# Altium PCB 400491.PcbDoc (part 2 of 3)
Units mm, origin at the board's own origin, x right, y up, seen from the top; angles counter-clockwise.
Board outline 85.6 x 53.98 mm, 4 copper layers (Top Layer, Mid-Layer 1, Mid-Layer 2, Bottom Layer), stack 1.528 mm thick; 280 components, 167 nets, 927 pads, 859 vias.
Unrouted connection lines stored in the file: 24.
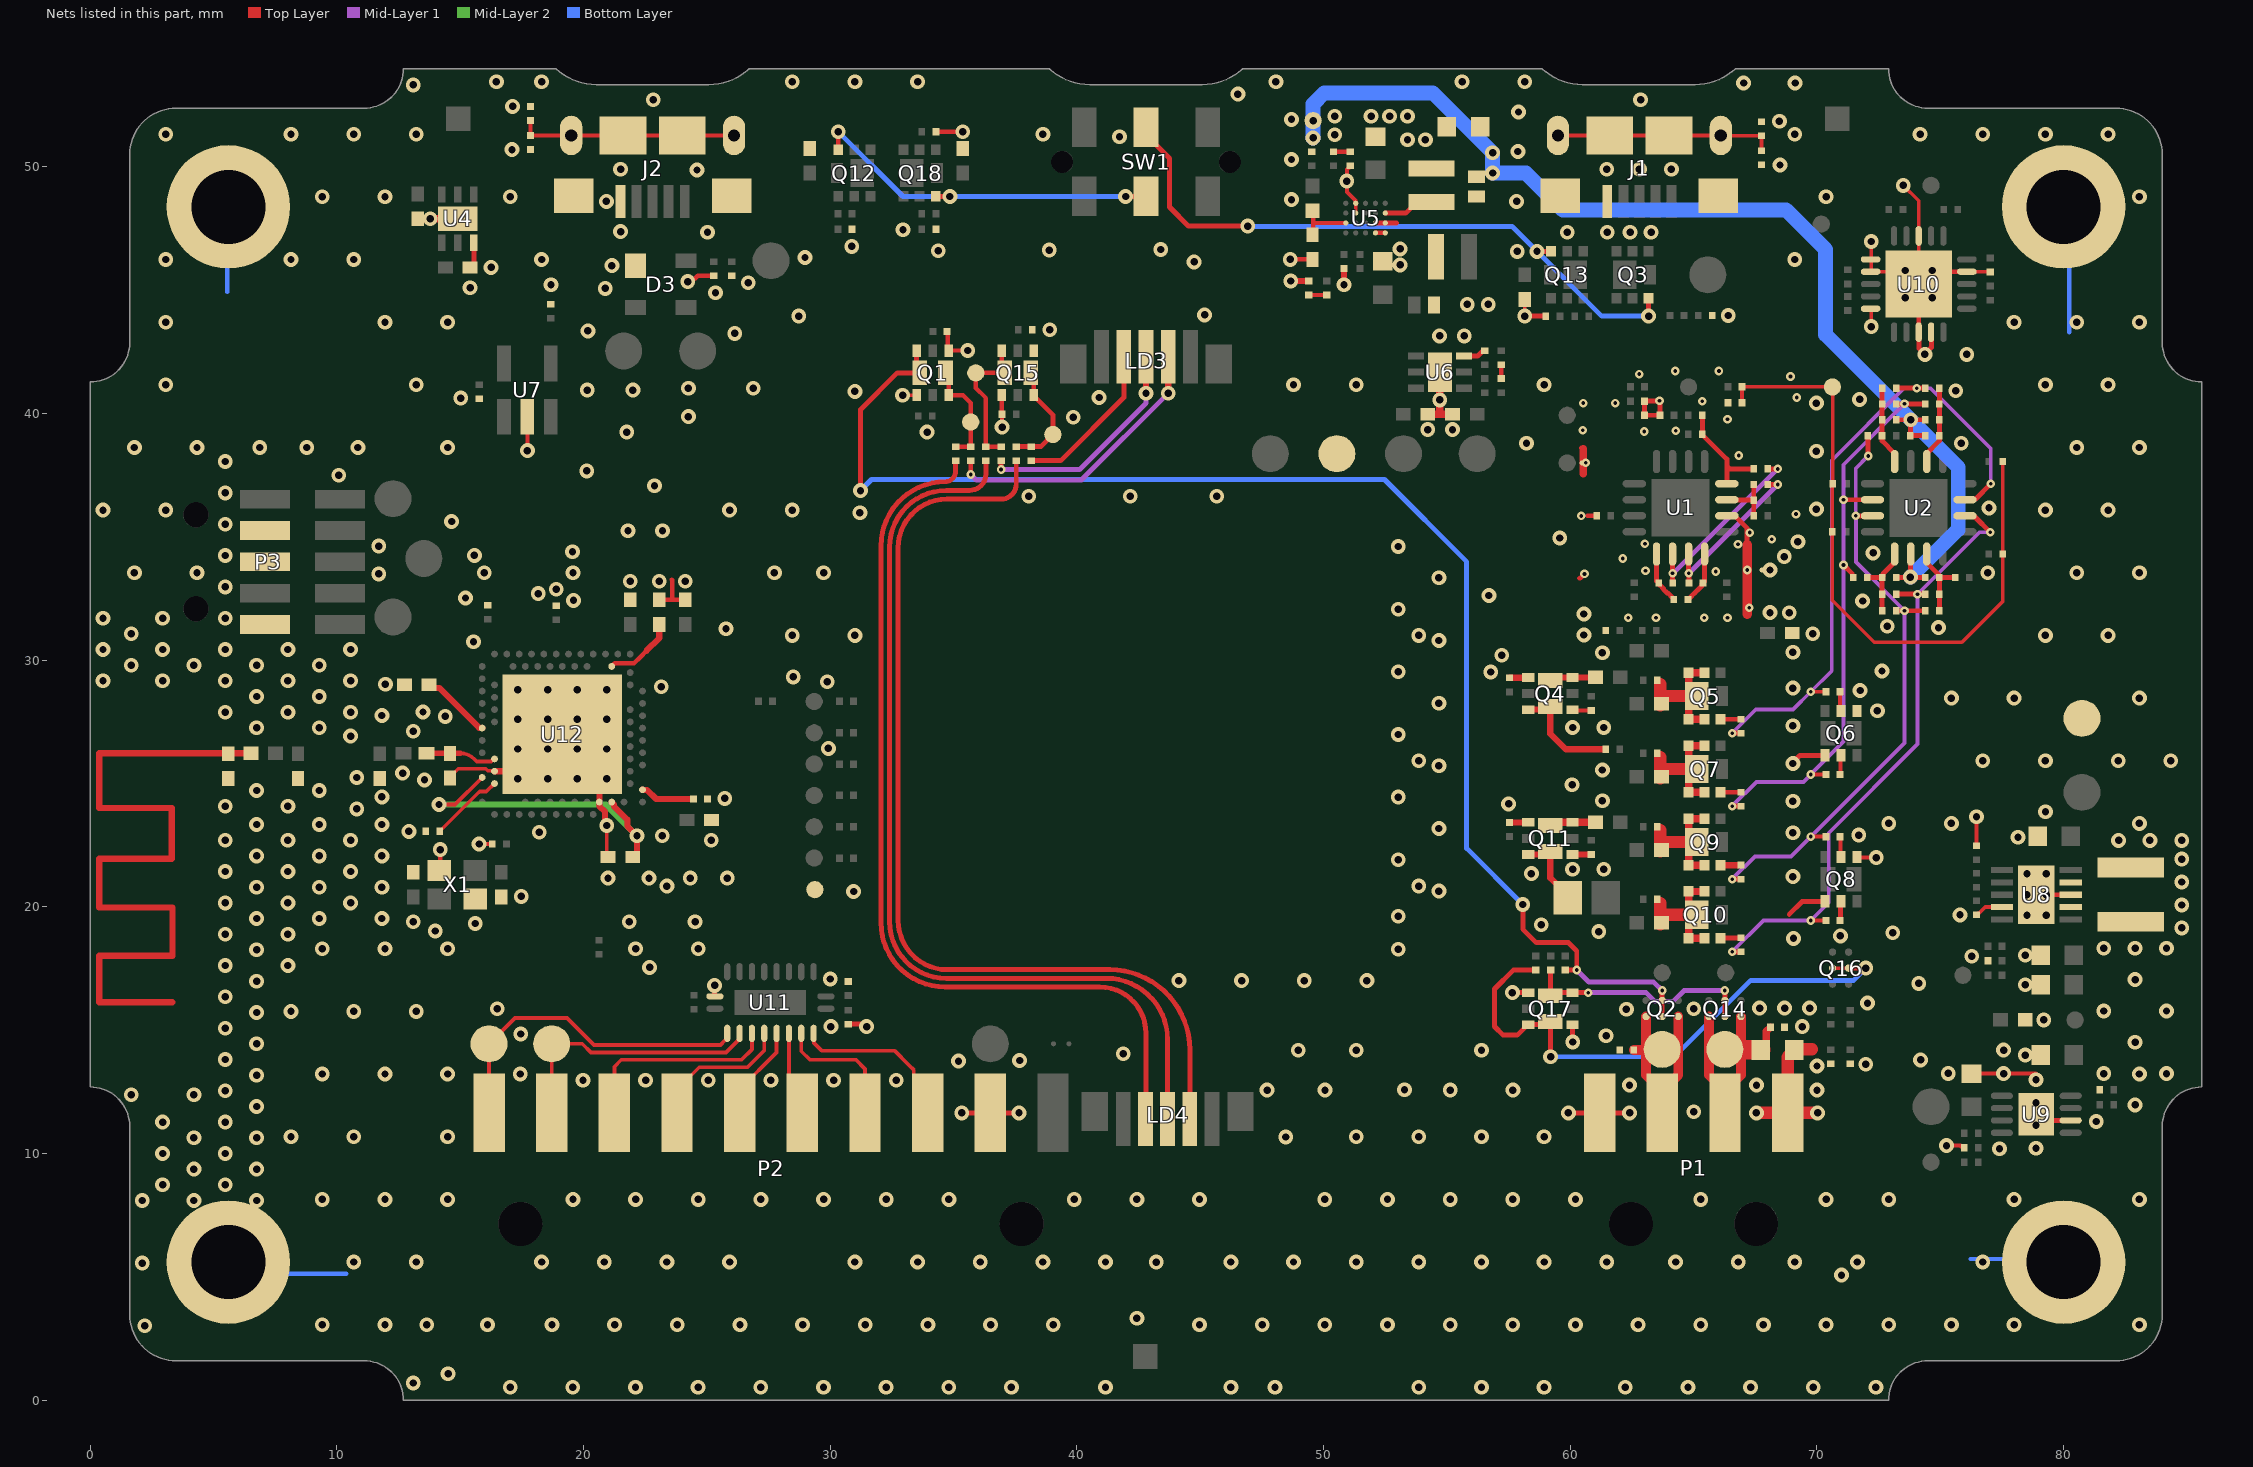
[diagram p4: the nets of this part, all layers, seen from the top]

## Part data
C1 C6: library part C0201-2.2p, "Chip Cap 0201", Part number IPS=N.A.
C2 C3 C9 C21 C22 C23 C24 C27 C46 C53 C54 C55 C60 C62 C67 C73 C75: library part C0201-100n, "Capacitor, X5R, ±10%", Part number IPS="00000001248, 00000002505"
C4 C8: library part C0201-1n0, "Capacitor, X7R, ±10%", Part number IPS=00000003206
C5 C38 C39 C44 C47 C48 C49 C50 C52: library part 0603-10u-10V-X7T-GRM188, "CAP CER 10UF 10V X7T 0603", Manufacturer=Murata, Manufacturer Part Number=GRM188D71A106MA73, Part number IPS=00000004696, Supplier Part Number 1=490-7200-1-ND
C7 C37 C42: library part C0201-2n2, "Capacitor, X7R, ±10%, 10V", Part number IPS=00000001778
C11 C14 C15 C16: library part C0201-470p, "Chip Cap 0201", Part number IPS=00000005775
C17 C19 C20 C30: library part C0201-10n, "Capacitor, X7R, ±10%", Part number IPS=00000003480
C18 C25 C26 C28 C34 C35 C41 C43 C71 C72 C74: library part C0402-4µ7, "Capacitor, X5R, ±20%", Part number IPS="00000001251, 00000007165", Supplier Part Number 1=490-13252-1-ND
C29 C33: library part C0201-4n7, "Chip Cap 0201", Part number IPS=00000001243
C40 C56 C61: library part C0402-1µ0, "Capacitor, X5R, ±5%, 6.3V", Part number IPS="00000007786, 00000003457", Supplier Part Number 1=1276-1444-1-ND
C45: library part C0201-1µ0, "Capacitor, X5R, ±10%", Part number IPS=00000001723, Supplier Part Number 1=1276-6795-1-ND
C57 C59: library part C0402-12p, "Capacitor, NP0, ±2%", Part number IPS=00000002398
C63: library part C0201-100p, "Capacitor, NP0, ±2%, 25V", Manufacturer=Murata, Manufacturer Part Number=GRM0335C1E101GA01, Part number IPS=00000007853
C65: library part C0402-0.8p, "Capacitor, NP0, ±5%", Manufacturer=Murata, Manufacturer Part Number=GRM1555C1HR80WA01D, Part number IPS=00000007782, Supplier Part Number 1=490-6270-1-ND
C66: library part C0402-0.5p, "Capacitor, NP0, ±0.05pF", Manufacturer=Murata, Manufacturer Part Number=GJM1555C1HR50WB01, Part number IPS=00000004293, Supplier Part Number 1=490-11250-1-ND
C68 C69: library part C0402-N.C., "Not mounted", Part number IPS=N.A.
C70: library part C0402-820p, "Capacitor, NP0, ±5%", Part number IPS=00000004365
D3: "Ultra low capacitance double rail-to-rail ESD protection diode", Manufacturer=NXP, Part number IPS=00000009951, Supplier Part Number 1=568-4140-1-ND
D4 D5: "DIODE SCHOTTKY 20V 0.5A DFN1006D-2/SOD882D", Manufacturer=NXP, Manufacturer Part Number="PMEG2005AELD, 315", Part number IPS=00000004695, Supplier Part Number 1=197-2709
ENCLOSURE1: library part Enclosure_PPK2, "PPK2 Moulded plastic casing", Manufacturer="Proto Labs, Inc.", Manufacturer Part Number="PPK plexi rev 1.2", Part number IPS=4971
Fid1 Fid2 Fid3: library part Fid-Mark-Round-Square, "Fiducial Mark", Part number IPS=N.A.
H1 H2 H3 H4: library part Hole_3MM_PT, "Regular Plate Through, 3mm hole", Manufacturer="Nordic Semiconductor", Part number IPS=N.A.
J1 J2: library part USB-Micro-B-RA-SMD-PiP, "MicroUSB-B-SMT", 2nd source part number=609-4616-1-ND, Manufacturer="Allen Creations Corp.", Manufacturer Part Number=AJU55-BS2111-L, Part number IPS=00000007790
L1 L2: library part EPL2014-472MLC, "Shielded Power Inductor EPL2014 Low DCR Ind 4.7 uH 20 % 650mA", Manufacturer=Coilcraft, Part number IPS=00000004697, Supplier Part Number 1=994-EPL2014-472MLB
L3: library part NR3015-1µ5-1.8A-48mOhm, "Ferrite Inductor, Shielded, 1,8A, 48mOhm", Manufacturer="Taiyo Yuden", Manufacturer Part Number=NR3015T1R5N, Part number IPS=00000004698, Supplier Part Number 1=587-2617-1-ND
L4: library part L0402-4n7, "Inductor, 160mA, ±0.1nH", Manufacturer=Murata, Manufacturer Part Number=LQP15MN4N7B02D, Part number IPS=00000004366, Supplier Part Number 1=490-1132-1-ND
LD3 LD4: library part MSL0104RGBU1, "High brightness, side view RGB LED", Manufacturer=ROHM, Part number IPS=00000007799, Supplier Part Number 1=MSL0104RGBU1CT-ND
P1: library part "Pin List Ang 1x4 SMD, 2.54mm", "Pin List 1x4, 2.54mm (100mil), Right Angled, SMD", Part number IPS=00000004780, Supplier Part Number 1=1125B-1104S0Z135CR02
P2: library part "Pin List Ang 1x10 SMD, 2.54mm", "Pin List 1x10, 2.54mm (100mil), Right Angled, SMD", Part number IPS=00000004781, Supplier Part Number 1=1125B-1110S0Z135CR02
P3: library part "Pin Header 2x5 SMD, 1.27mm, Angled", "Pin Header 2x5, 1.27mm (50mil)", Manufacturer=W-CON, Manufacturer Part Number=1325B-1205S0Z080CR02, Part number IPS=00000007800
Q1 Q4 Q6 Q8 Q11 Q15 Q17: "Dual N Ch MOFET, 3.3A, 45mOhm @ 5A, 4.5V, 730mW", Manufacturer="Diodes Incorporated", Manufacturer Part Number=DMN2050LFDB-7, Part number IPS=00000004782, Supplier Part Number 1=DMN2050LFDB-7DICT-ND
Q2 Q14 Q16: "Dual MOSFET, Dual N Channel, 13 A, 12 V, 0.009 ohm, 4.5 V, 2.5 V", Manufacturer="ON Semiconductor", Manufacturer Part Number=EFC6604R-TR, Part number IPS=00000004783, Supplier Part Number 1=863-EFC6604R-TR
Q3 Q5 Q7 Q9 Q10 Q12 Q13 Q18: "P Ch MOFET, 11A, 30mOhm max, 2W", Manufacturer="Diodes Incorporated", Part number IPS=00000004784, Supplier Part Number 1=DMP1009UFDF-7DICT-ND
R1 R2 R6 R10 R75: library part R0201-20k_0.1%, "Resistor, ±0.1%, 0.031W", Part number IPS=00000004785
R3 R7 R8 R9 R58 R60 R62 R72: library part R0201-10k_0.1%, "Resistor, ±0.1%, 0.031W", Part number IPS=00000004786
R4 R71: library part R0201-1k0, "Resistor, ±1%, 0.05W", Part number IPS=00000005786
R5: library part R0201-2k1, "RES SMD 2.1K OHM 1% 1/20W 0201", Manufacturer=Panasonic, Manufacturer Part Number=ERJ-1GEF2101C, Part number IPS=00000004787, Supplier Part Number 1=P2.10KABCT-ND
R11 R15 R20 R24 R25 R28 R29: library part R0201-8k2, "Resistor, ±1%, 0.05W", Part number IPS=00000004788
R12 R21 R26 R30: library part R0201-3k0, "Resistor, ±1%, 0.05W", Part number IPS=00000001688
R13 R23 R27 R31 R32: library part R0201-6k8, "Resistor, ±1%, 0.05W", Part number IPS=00000001705
R14: library part R0201-220k, "Resistor, ±1%, 0.05W", Part number IPS=00000004789
R16 R34 R90 R110: library part R0201-120k, "Resistor, ±1%, 0.05W", Part number IPS=00000001425
R17 R74 R78: library part R0201-56k, "Resistor, ±1%, 0.05W", Part number IPS=00000007882
R18 R37 R61 R67 R68 R83 R88 R102 R104 R105: library part R0201-100k, "Resistor, ±1%, 0.05W", Part number IPS=00000001419
R19 R22 R43 R47 R51 R55 R81 R82: library part R0201-4k7, "Resistor, ±1%, 0.05W", Part number IPS=00000001706
R33 R41: library part R0402-1k0_0.1%, "Resistor, ±0.1%, 0.063W", Part number IPS=00000004790
R35 R39 R59 R63 R64 R70 R99 R100 R101 R106 R107 R108 R109: library part R0201-1M0, "Resistor, ±1%, 0.05W", Part number IPS=00000001418
R36 R91 R92 R111: library part R0201-30k, "Resistor, ±1%, 0.05W", Part number IPS=00000004318
R38: library part R0805-100, "Resistor, ±1%, 0.125W", Part number IPS=00000004791
R40: library part R0402-100k_0.1%, "Resistor, ±0.1%, 0.063W", Part number IPS=00000004792, Supplier Part Number 1=P100KDCCT-ND
R42: library part R0402-110, "Resistor, ±1%, 0.063W", Part number IPS=00000004793, Supplier Part Number 1=541-110LCT-ND
R44 R45 R48 R49 R52 R53 R56 R57 R94 R95 R97 R98: library part R0201-47R, "Resistor, ±1%, 0.05W", Part number IPS=00000004794
R46: library part R0402-11R, "Resistor, ±1%, 0.063W", Part number IPS=00000007807, Supplier Part Number 1=214-0577
R50: library part R0402-1R0, "Resistor, ±1%, 0.063W", Part number IPS=00000004795
R54: library part R0402-0R051, "RES SMD 0.051 OHM 1% 1/4W 0402", Manufacturer=Panasonic, Manufacturer Part Number=ERJ-2BWFR051X, Part number IPS=00000004796, Supplier Part Number 1=P.051ATCT-ND
R73: library part R0201-180k, "Resistor, ±1%, 0.05W", Part number IPS=00000004797
R76: library part R0402-160k_0.1%, "Resistor, ±0.1%, 0.063W", Part number IPS=00000004798, Supplier Part Number 1=A119926CT-ND
R77 R84 R85 R112: library part R0201-330k, "Resistor, ±1%, 0.05W", Part number IPS=00000001424
R79 R116: library part R0201-560k, "Resistor, ±1%, 0.05W", Part number IPS=00000004799
R80: library part R0201-68k, "Resistor, ±1%, 0.05W", Part number IPS=00000004800
R86: library part R0201-33k, "Resistor, ±1%, 0.05W", Part number IPS=00000001708
R87: library part R0201-82k, "Resistor, ±1%, 0.05W", Part number IPS=00000004801
R89 R114 R115: library part R0201-0R, "Resistor, ±5%, 0.05W", Part number IPS=00000003245
R93 R96: library part R0201-180, "Resistor, ±1%, 0.05W", Part number IPS=00000005783
R103: library part R0402-0R, "Resistor, ±5%, 0.063W", Part number IPS=00000007128, Supplier Part Number 1=146-9661
R113: library part NCP15XH103F03RC, "THERMISTOR 10K OHM NTC 0402 SMD", Manufacturer=Murata, Part number IPS=00000007808, Supplier Part Number 1=490-4801-1-ND
SB1 SB2: library part "NetTie 0.2mm", "Net Tie", Part number IPS=N.A.
SB3: Part number IPS=N.A.
SCREW1 SCREW2 SCREW3 SCREW4: library part Screw_25x50_pan_tx, "Pan head, torx, 2.5x5mm screw", Manufacturer=Bossard, Manufacturer Part Number=3205129, Part number IPS=4972
SW1: library part Switch-Slide-RA-J-Lead-DPDT-8.5x3.5mm_Copal, "SMD slide Switch (ON-ON)", Manufacturer="Copal Electronics Inc", Manufacturer Part Number=CL-SB-22A-11T, Part number IPS=00000007811, Supplier Part Number 1=563-1340-1-ND
TP1 TP2 TP3 TP4 TP5 TP10 TP18 TP19 TP21 TP22 TP23 TP24 TP26 TP30 TP31 TP32 TP33 TP37 TP38 TP39 TP40 TP41: library part TP_SMD_Ø0.7MM, "0.7mm circular SMD testpad", Manufacturer="Nordic Semiconductor", Part number IPS=N.A.
TP6 TP7 TP8 TP9 TP11 TP12 TP13 TP14 TP15 TP16 TP17 TP20 TP25 TP27 TP28 TP29 TP34 TP35 TP36: library part TP_SMD_Ø1.5MM, "1.5mm circular SMD testpad", Manufacturer="Nordic Semiconductor", Part number IPS=N.A.
U1 U2: library part ADA4622-4, "J-FET Amplifier 4 Circuit Rail-to-Rail 16-LFCSP (4x4)", Manufacturer="Analog Devices", Manufacturer Part Number=ADA4622-4ACPZ-RL, Part number IPS=00000004963, Supplier Part Number 1=ADA4622-4ACPZ-R7-ND
U4: "Ultralow Noise, 200 mA,CMOS Linear Regulator", Manufacturer="Analog Devices", Manufacturer Part Number=ADP151ACPZ-3.3-R7, Part number IPS=00000004803, Supplier Part Number 1=ADP151ACPZ-3.3-R7CT-ND
U5: "Boost Switching Regulator IC Positive and Negative (Dual Rail) Adjustable 0.8V 2 Output 600mA, 1A 20-UFBGA,", Manufacturer="Analog Devices", Manufacturer Part Number=ADP5072ACBZ-R7, Part number IPS=00000004804, Supplier Part Number 1=ADP5072ACBZ-R7-ND
U6: "20 V, 200 mA, Low Noise,CMOS LDO Linear Regulator", Manufacturer="Analog Devices", Manufacturer Part Number=ADP7118ACPZN-R7, Part number IPS=00000004964, Supplier Part Number 1=ADP7118ACPZN-R7TR-ND
U7: library part 24CW160T-I/OT, "16 Kbit I2C Serial EEPROM with Software Write Protection, 1.6-5.5 V Supply", Manufacturer=Microchip, Part number IPS=00000004049, Supplier Part Number 1=24CW160T-I/OTCT-ND
U8: "Buck-Boost Switching Regulator IC Positive Adjustable 2.8V 1 Output 1A", Manufacturer="Analog Devices", Manufacturer Part Number=ADP2504ACPZ-R7, Part number IPS=00000004965, Supplier Part Number 1=ADP2504ACPZ-R7CT-ND
U9: "LDO, Adjustable, 1 Output 1A, 8-LFCSP-WD (3x3)", Manufacturer="Analog Devices", Manufacturer Part Number=ADP1708ACPZ-R7, Part number IPS=00000004966, Supplier Part Number 1=ADP1708ACPZ-R7CT-ND
U10: "Quad Digital Potentiometer, 100k, 257 taps, I2C interface, Volatile Memory, 1.8-5.5V", Manufacturer="Microchip Technology", Manufacturer Part Number=MCP4451-104E/ML, Part number IPS=00000004805, Supplier Part Number 1=MCP4451-104E/ML-ND
U11: library part FXMA108BQX, "8-bit bidirectional voltage-level translator with auto-direction sensing", Manufacturer="Fairchild Semiconductor", Part number IPS=00000004806, Supplier Part Number 1=FXMA108BQXFSCT-ND
U12: library part nRF52840-QIAAD0, "Multi-protocol Bluetooth Low Energy, IEEE 802.15.4, ANT and 2.4GHz proprietary system-on-chip", Manufacturer="Nordic Semiconductor", Part number IPS=80000001648
X1: library part XTAL_SMD2016_32MHz_8pF_General, "XTAL SMD 2016, 32MHz, Cl=8pF, Total Tol: ±40ppm", Part number IPS=00000007827

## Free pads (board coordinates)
  round 0.3 on Mech16: 1(15.89,26.75) 1(16.39,27.5) 1(16.39,28) 1(17.14,29.75) 1(17.64,29.75) 1(18.14,29.75) 1(19.14,24.25) 1(19.14,29.75) 1(19.64,24.25) 1(19.64,29.75) 1(20.14,24.25) 1(20.14,29.75) 1(20.64,29.75) 1(21.89,26) 1(21.89,26.5) 1(21.89,27) 1(21.89,28)
  round 0.6 on Mech16: 1(17.34,25.2) 1(17.34,26.4) 1(17.34,27.6) 1(17.34,28.8) 1(18.54,25.2) 1(18.54,26.4) 1(18.54,27.6) 1(18.54,28.8) 1(19.74,25.2) 1(19.74,26.4) 1(19.74,27.6) 1(19.74,28.8) 1(20.94,25.2) 1(20.94,26.4) 1(20.94,27.6) 1(20.94,28.8) 1(63.921,35.631) 1(63.921,36.731) 1(65.021,35.631) 1(65.021,36.731) 1(73.575,44.7) 1(73.575,45.8) 1(73.575,35.631) 1(73.575,36.731) 1(74.675,44.7) 1(74.675,45.8) 1(74.675,35.631) 1(74.675,36.731) 1(78.515,19.656) 1(78.515,20.5) 1(78.515,21.344) 1(78.88,11.144) 1(78.88,12.069) 1(78.88,12.994) 1(79.29,19.656) 1(79.29,20.5) 1(79.29,21.344)

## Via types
v1: diameter 0.6, hole 0.3, Top Layer to Bottom Layer, 767 vias
v2: diameter 0.35, hole 0.15, Top Layer to Mid-Layer 1, 92 vias

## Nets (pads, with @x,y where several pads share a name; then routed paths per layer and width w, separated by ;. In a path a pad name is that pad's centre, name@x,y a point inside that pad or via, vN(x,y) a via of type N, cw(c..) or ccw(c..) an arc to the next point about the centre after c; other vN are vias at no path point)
AGND: C2.2 C4.1 C7.1 C8.1 R9.1 SB1.1 SB2.2 U1.10 | length 8.6
  Top Layer w0.2: 60.373,33.323 60.398,33.323 v2(60.575,33.5) ; 60.45,38.6 60.475,38.575 ; 60.706,35.856 C2.2@61.071,35.856 ; U1.10@66.346,35.856 66.671,35.856 67.171,35.356 67.171,34.669 ; C8.1@63.01,39.931 C4.1@63.636,39.931 63.631,39.937 63.631,40.519 63.625,40.525 v2(63.616,40.516) 63.019,40.516 R9.1@63.01,40.506 C8.1@63.01,39.931
  Top Layer w0.3: 60.525,37.556 60.525,38.575
  Top Layer w0.4: 67.171,31.875 v2(67.171,33.656) 67.171,34.669
  other v2: 62.35,31.725 63.475,31.725 65.425,31.725 66.375,31.725 67.25,32.125 65.9,33.6 63.05,33.625 62.125,34.125 66.8,34.7 63.025,34.725 68.164,34.901 67.275,35.175 60.45,35.85 69.15,35.925 60.625,38 66.825,38.3 63,39.275 64.275,39.3 60.5,39.325 66.375,39.775 60.525,40.425 61.825,40.425 65.35,40.5 69.175,40.65 68.925,41.5 62.8,41.6 64.25,41.725 66.025,41.725
ANT: C69.2 R103.2 | length 31
  Top Layer w0.254: 3.327,16.137 0.363,16.137 0.363,18.017 3.332,18.017 3.332,19.973 0.363,19.973 0.363,21.954 3.307,21.954 3.307,24.011 0.363,24.011 0.363,26.229 R103.2@6.515,26.229
ANT': C65.2 L4.1 U12.H23 | length 2.8
  Top Layer w0.145: 15.566,25.997 15.668,25.895 16.25,25.895 16.355,26 U12.H23@16.39,26
  Top Layer w0.15: 15.005,26.229 cw(c15.005,25.436) 15.566,25.997
  Top Layer w0.22: L4.1@13.691,26.229 15.005,26.229
AUTO_SW1: R15.2 R21.2 R44.1 R45.2 U2.15 | length 27.2
  Top Layer w0.15: v2(69.75,28.718) R45.2@70.365,28.718
  Top Layer w0.2: v2(66.56,27.043) R44.1@66.921,27.043 ; R21.2@73.21,41.031 R15.2@74.39,41.031 ; U2.15@76,36.506 76.019,36.525 76.425,36.525 v2(77.05,37.15)
  Mid-Layer 1 w0.15: v2(66.56,27.043) 67.517,28 69.032,28 v2(69.75,28.718) 70.6,29.568 70.6,38.1 73.531,41.031 74.594,41.031 77.05,38.575 v2(77.05,37.15)
  other v2: 74.05,41.031
AUTO_SW2: R13.1 R24.2 R26.2 R48.1 R49.2 U2.6 | length 24.3
  Top Layer w0.15: v2(69.75,25.368) R49.2@70.365,25.368
  Top Layer w0.2: v2(66.56,24.085) R48.1@66.921,24.085 ; v2(71.075,33.863) 71.43,33.508 71.43,33.391 R26.2@71.465,33.356 ; v2@71.075,36.506 U2.6@72.25,36.506 ; R24.2@73.21,40.389 R13.1@74.39,40.389
  Mid-Layer 1 w0.16: v2(66.56,24.085) 67.545,25.07 69.452,25.07 v2(69.75,25.368) 69.75,25.385 71.075,26.71 v2(71.075,33.863) v2(71.075,36.5) 71.075,37.925 v2(73.55,40.4)
AUTO_SW3: R23.1 R28.2 R30.2 R52.1 R53.2 U2.7 | length 25.6
  Top Layer w0.15: v2(69.75,22.851) R53.2@70.365,22.851
  Top Layer w0.2: v2(66.56,21.126) R52.1@66.921,21.126 ; v2(71.572,35.856) U2.7@72.25,35.856 ; R23.1@72.065,39.106 72.075,39.096 v2(72.075,38.281) ; R28.2@73.21,32.006 R30.2@74.39,32.006
  Mid-Layer 1 w0.16: v2(66.56,21.126) 67.483,22.05 68.949,22.05 69.714,22.815 v2(69.75,22.851) 73.55,26.651 v2(73.55,32.006) 71.575,33.981 71.575,35.853 v2(71.572,35.856) 71.572,37.778 v2(72.075,38.281)
AUTO_SW4: R27.1 R32.2 R56.1 R57.2 U2.14 | length 26.1
  Top Layer w0.15: v2(69.75,19.451) R57.2@70.365,19.451
  Top Layer w0.2: v2(66.56,18.181) R56.1@66.921,18.181 ; R27.1@73.21,32.681 R32.2@74.39,32.681 ; U2.14@76,35.856 76.352,35.856 76.402,35.806 76.407,35.806 v2(77.025,35.187)
  Mid-Layer 1 w0.15: v2(66.56,18.181) 67.828,19.45 v2(69.75,19.451) 70.475,20.176 70.475,23 74.075,26.6 v2(74.075,32.675) ; v2@74.15,32.75 76.587,35.187 v2(77.025,35.187)
DEC1: C60.1 U12.C1 | length 2.2
  Top Layer w0.25: U12.C1@22.39,24.75 22.395,24.745 22.57,24.745 22.94,24.375 C60.1@24.465,24.375
DEC3: C63.1 U12.D23 | length 3
  Top Layer w0.15: C63.1@14.175,23.075 14.175,23.09 14.235,23.15 14.255,23.15 15.748,24.644 15.771,24.644 15.802,24.675 16.059,24.675 16.384,25 U12.D23@16.39,25
DEC4_6: C56.2 U12.B5 U12.E24 | length 13.4
  Top Layer w0.15: v1(14.14,24.15) 14.79,24.15 U12.E24@15.89,25.25
  Top Layer w0.25: U12.B5@21.14,24.25 21.14,24.243 21.227,24.156 21.227,24.079 21.469,23.837 21.775,23.532 21.775,23.278 v1(22.165,22.888) C56.2@22.165,22.025
  Mid-Layer 2 w0.25: v1(14.14,24.15) 20.903,24.15 v1(22.165,22.888)
DK_LP_D0: P2.1 TP36.1 U11.12 | length 13.7
  Top Layer w0.15: P2.1@16.17,11.65 TP36.1@16.17,14.45 17.22,15.5 19.325,15.5 20.425,14.4 25.548,14.4 25.748,14.6 25.825,14.677 U11.12@25.825,14.875
DK_LP_D1: P2.2 TP35.1 U11.13 | length 11
  Top Layer w0.15: P2.2@18.71,11.65 TP35.1@18.71,14.45 19.951,14.45 20.301,14.1 25.775,14.1 26.325,14.65 U11.13@26.325,14.875
DK_LP_D2: P2.3 U11.14 | length 8.4
  Top Layer w0.15: P2.3@21.25,11.65 21.25,13.525 21.525,13.8 26.4,13.8 26.825,14.225 U11.14@26.825,14.875
DK_LP_D3: P2.4 U11.15 | length 5.8
  Top Layer w0.15: P2.4@23.79,11.65 23.79,12.605 24.685,13.5 26.647,13.5 27.325,14.178 U11.15@27.325,14.875
DK_LP_D4: P2.5 U11.16 | length 3.8
  Top Layer w0.15: P2.5@26.33,11.65 26.33,12.605 27.825,14.1 U11.16@27.825,14.875
DK_LP_D5: P2.6 U11.17 | length 3.2
  Top Layer w0.15: P2.6@28.325,12.42 U11.17@28.325,14.875 ; P2.6@28.35,12.17 P2.6@28.87,11.65
DK_LP_D6: P2.7 U11.18 | length 5.4
  Top Layer w0.15: U11.18@28.825,14.875 28.825,14.15 29.175,13.8 31.044,13.8 31.41,13.434 P2.7@31.41,11.65
DK_LP_D7: P2.8 U11.19 | length 6.9
  Top Layer w0.15: U11.19@29.325,14.875 29.344,14.856 29.344,14.481 29.65,14.175 32.6,14.175 33.175,13.6 33.39,13.385 33.39,12.21 P2.8@33.95,11.65
EXT_POWER_IN: C5.1 C67.1 P1.3 Q14.4 Q14.6 TP7.1 | length 9.1
  Top Layer w0.3: C5.1@67.713,14.213 67.95,14.45 67.95,14.96 C67.1@68.115,15.125
  Top Layer w0.4: Q14.4@65.616,15.556 65.616,13.181 66.266,12.531 66.916,13.181 66.916,14.213 Q14.6@66.916,15.556
  Top Layer w0.6: TP7.1@66.266,14.225 66.279,14.213 TP7.1@66.916,14.213
  Top Layer w0.8: TP7.1@66.916,14.213 C5.1@67.712,14.213
EXT_POWER_OUT: C17.2 P1.2 Q2.4 Q2.6 TP6.1 | length 7.8
  Top Layer w0.4: C17.2@62.575,14.2 TP6.1@63.076,14.2 ; Q2.4@63.076,15.556 TP6.1@63.076,14.2 ; TP6.1@63.726,14.225 63.701,14.2 TP6.1@63.076,14.2 ; Q2.6@64.376,15.556 64.376,13.181 63.726,12.531 63.076,13.181 TP6.1@63.076,14.2
GND: C3.2 C5.2 C17.1 C18.2 C19.1 C25.1 C26.1 C27.2 C28.2 C29.2 C30.2 C33.2 C34.2 C35.1 C37.1 C38.1 C39.2 C40.1 C41.2 C42.1 C43.1 C44.1 C46.2 C47.2 C48.2 C49.2 C50.2 C52.2 C53.1 C54.2 C55.2 C56.1 C57.2 C59.2 C60.2 C61.2 C62.2 C63.2 C65.1 C66.1 C67.2 C68.1 C69.1 C70.2 C71.2 C72.2 C73.2 C74.2 C75.2 D3.1 H1.1 H2.1 H3.1 H4.1 J1.5 J2.5 L2.1 P1.1 P1.4 P2.9 P3.3 P3.5 P3.9 Q1.1 Q1.4 Q4.1 Q4.4 Q6.1 Q6.4 Q8.1 Q8.4 Q11.1 Q11.4 Q15.1 Q15.4 Q17.1 Q17.4 R18.1 R35.1 R36.1 R59.1 R61.2 R63.2 R64.2 R67.2 R70.2 R75.1 R80.1 R83.1 R86.1 R87.1 R91.1 R92.1 R99.1 R100.1 R101.1 R108.1 R109.1 R111.1 R113.1 R115.1 SB1.2 TP26.1 TP28.1 TP29.1 U4.3 U4.7 U5.A4 U5.B4 U5.D1 U5.D2 U6.3 U6.7 U7.2 U8.3 U8.9 U8.11 U9.2 U9.9 U10.1 U10.2 U10.5 U10.8 U10.9 U10.14 U10.18 U10.21 U11.10 U12.74 U12.B7 U12.F23 X1.2 X1.4 | length 92.2
  Top Layer w0.145: 15.545,25.605 16.037,25.605 16.118,25.524 16.366,25.524 U12.F23@16.39,25.5
  Top Layer w0.15: C65.1@14.588,25.225 14.588,25.275 14.919,25.605 15.545,25.605 ; C56.1@20.94,22.15 v1(20.94,23.3) ; v1(32.935,40.745) Q1.1@33.5,40.745 ; U5.D2@51.3,48.125 U5.D1@51.3,48.525 ; R59.1@57.535,29.285 R59.1@57.543,29.292 ; v1(58.15,43.95) C25.1@58.15,44.625 ; Q4.1@58.278,29.292 Q4.1@58.285,29.3 ; Q6.1@71.625,27.988 Q6.1@71.63,27.993 ; U10.2@72.199,45.75 v1(72.199,46.976) ; U10.5@72.2,44.25 72.201,44.249 v1(72.201,43.524) ; U10.2@72.2,45.75 U10.21@73.625,45.75 ; v1(73.5,49.25) 74.126,48.624 74.126,47.176 74.125,47.175 U10.21@74.125,45.25 ; U10.14@76.05,45.75 76.056,45.744 77.021,45.744 C53.1@77.026,45.739 ; C3.2@76.428,19.646 C3.2@76.465,19.684 76.525,19.744 76.57,19.744 76.82,19.994 U8.9@77.495,19.994 ; R115.1@76.466,22.48 v1@76.466,23.409
  Top Layer w0.175: X1.4@14.154,21.48 14.19,21.516 v1(14.19,22.325) ; v1(15.765,22.55) 16.24,22.55 16.265,22.525 16.298,22.557 C62.2@16.305,22.55 ; v1(17.725,38.5) 17.725,39.775 17.775,39.825 U7.2@17.725,39.875 ; C71.2@23.065,32.45 23.595,32.45 ; 23.575,33.275 23.595,33.255 23.595,32.45 ; C72.2@24.125,32.45 23.595,32.45 ; v1@24.225,45.3 24.34,45.3 24.63,45.59 C30.2@25.275,45.59 ; U11.10@25.311,16.389 U11.10@25.325,16.375 ; R101.1@34.735,43.325 34.768,43.292 34.768,42.587 34.8,42.555 35.5,42.555 35.575,42.48 v1@35.575,42.535 ; Q15.4@36.95,40.745 36.958,40.738 R99.1@36.958,40.083 ; v1(36.965,39.45) R99.1@36.965,39.975 ; v1(48.65,46.25) C40.1@49.55,46.25 ; C37.1@49.385,45.375 C37.1@49.4,45.375 ; C42.1@51.1,50.04 51.085,50.04 51.038,49.993 51.038,49.978 50.95,49.89 50.95,48.98 51.293,48.636 51.293,48.532 U5.D1@51.3,48.525 ; U5.B4@52.1,47.325 U5.A4@52.5,47.325 ; Q4.4@60.095,28 60.13,27.965 R35.1@60.845,27.965 ; Q8.1@71.625,22.031 71.656,22 v1(72.4,22) ; U10.21@74.625,45.75 U10.14@76.05,45.75 ; v1(75.25,10.325) 75.815,10.325 75.84,10.3 75.918,10.3 75.965,10.252 R87.1@75.965,10.237 ; C50.2@76.265,13.244 v1@78.865,13.244
  Top Layer w0.2: C35.1@15.4,45.922 15.55,46.072 U4.3@15.55,46.922 ; U11.10@25.311,16.389 v1(25.311,16.819) ; C55.2@30.725,15.248 v1@31.23,15.248 ; R67.2@34.285,51.425 v1(35.375,51.425) ; v1(35.33,11.65) P2.9@36.49,11.65 v1(37.65,11.65) ; U6.3@55.696,42.334 56.247,42.334 56.428,42.515 56.49,42.515 R80.1@56.525,42.55 ; v1(57.655,16.525) Q17.1@58.285,16.525 ; v1(58.15,43.95) R18.1@59.01,43.95 ; v1(59.925,11.65) v1(62.405,11.65) ; Q17.4@60.095,15.225 60.097,15.222 60.097,14.478 v1@60.1,14.475 ; 68.875,19.7 69.396,20.221 Q8.4@70.325,20.221 ; v1@68.875,25.814 68.983,25.814 69.307,26.138 Q6.4@70.325,26.138 ; U10.21@74.125,44.463 74.125,43.325 74.135,43.315 74.135,42.64 v1(74.376,42.399) 74.376,42.417 74.635,42.675 74.635,43.315 U10.9@74.625,43.325 ; U9.9@79.14,11.344 U9.2@80.285,11.344 ; U8.11@79.492,20.494 U8.3@80.24,20.494
  Top Layer w0.25: U12.F23@16.39,25.5 17.64,25.5 v1(18.54,26.4) U12.74@19.14,27 20.64,25.5 U12.B7@20.64,24.25 20.645,24.245 20.645,24.079 20.873,23.85 20.873,23.367 v1(20.94,23.3)
  Top Layer w0.254: v1(48.67,45.375) C37.1@49.4,45.375 ; v1(50.825,45.225) R75.1@50.825,45.88 ; R109.1@57.535,23.422 57.536,23.424 58.284,23.424 Q11.1@58.285,23.425 ; R59.1@57.543,29.292 Q4.1@58.278,29.292 ; Q11.4@60.095,22.125 60.096,22.126 60.844,22.126 R108.1@60.845,22.128
  Top Layer w0.3: C34.2@13.275,47.9 U4.7@14.9,47.9 ; C41.2@54.225,39.975 54.655,39.975 ; 54.713,39.975 54.713,40.479 v1(54.708,40.553) 54.708,41.674 U6.7@54.718,41.684 ; 54.723,39.975 C43.1@55.225,39.975
  Top Layer w0.5: v1(67.545,11.65) P1.4@68.81,11.65 ; 69.8,14.225 69.1,14.225 C5.2@69.075,14.2 69.075,14.175 68.81,13.91 P1.4@68.81,11.65 ; v1(70.025,11.65) P1.4@68.81,11.65
  Bottom Layer w0.175: 5.55,44.925 5.55,48.33 H4.1@5.6,48.38 ; H3.1@5.6,5.6 6.075,5.125 10.375,5.125 ; 76.225,5.725 79.875,5.725 H2.1@80,5.6 ; H1.1@80,48.38 80.225,48.155 80.225,43.3
  other v1: 17.025,0.525 19.565,0.525 22.105,0.525 24.645,0.525 27.185,0.525 29.725,0.525 32.265,0.525 34.805,0.525 37.345,0.525 41.16,0.525 46.24,0.525 48.03,0.525 53.86,0.525 56.4,0.525 58.94,0.525 62.23,0.525 64.77,0.525 67.31,0.525 69.85,0.525 72.39,0.525 13.095,0.7 14.51,1.075 2.21,3.02 9.41,3.065 11.95,3.065 13.64,3.065 16.105,3.065 18.72,3.065 21.26,3.065 23.8,3.065 26.34,3.065 28.88,3.065 31.42,3.065 33.96,3.065 36.5,3.065 39.04,3.065 44.97,3.065 47.51,3.065 50.05,3.065 52.59,3.065 55.13,3.065 57.67,3.065 60.21,3.065 62.75,3.065 65.29,3.065 67.83,3.065 70.37,3.065 72.91,3.065 75.45,3.065 77.99,3.065 83.07,3.065 42.43,3.325 70.995,5.075 2.11,5.56 10.68,5.605 13.22,5.605 18.3,5.605 20.84,5.605 23.38,5.605 25.92,5.605 31,5.605 33.54,5.605 36.08,5.605 38.62,5.605 41.16,5.605 43.215,5.6 46.24,5.605 48.78,5.605 51.32,5.605 53.86,5.605 56.4,5.605 58.94,5.605 61.48,5.605 64.27,5.605 66.81,5.605 69.1,5.605 71.64,5.605 76.72,5.605 2.11,8.1 4.205,8.1 6.745,8.1 9.41,8.145 11.95,8.145 14.49,8.145 19.57,8.145 22.11,8.145 24.65,8.145 27.19,8.145 29.73,8.145 32.27,8.145 34.81,8.145 39.89,8.145 42.43,8.145 44.97,8.145 50.05,8.145 52.59,8.145 55.13,8.145 57.67,8.145 60.21,8.145 65.29,8.145 70.37,8.145 72.91,8.145 77.99,8.145 83.07,8.145 2.935,8.735 5.475,8.735 4.205,9.37 6.745,9.37 2.935,10.005 5.475,10.005 77.4,10.2 78.88,10.219 4.205,10.64 6.745,10.64 48.465,10.675 8.14,10.685 10.68,10.685 14.49,10.685 51.32,10.685 53.86,10.685 56.4,10.685 58.94,10.685 78.88,11.144 2.935,11.275 5.475,11.275 81.325,11.3 65.003,11.698 6.745,11.91 82.898,11.973 78.88,12.069 1.665,12.385 4.205,12.385 5.475,12.545 47.71,12.575 50.055,12.575 55.135,12.575 57.675,12.575 70,12.575 53.28,12.585 62.4,12.775 67.55,12.775 19.975,12.975 22.515,12.975 25.055,12.975 27.595,12.975 30.135,12.975 32.675,12.975 78.88,12.994 6.745,13.18 9.41,13.225 11.95,13.225 14.49,13.225 17.435,13.225 81.628,13.242 83.07,13.225 84.168,13.242 75.325,13.25 77.565,13.244 70,13.55 71.975,13.625 35.2,13.75 37.675,13.775 74.2,13.8 5.475,13.815 78.44,13.994 41.875,14.05 48.975,14.19 51.32,14.19 56.4,14.19 77.565,14.194 6.745,14.45 82.898,14.513 60.1,14.525 61.453,14.775 17.45,14.85 5.475,15.085 30.025,15.15 31.475,15.15 69.4,15.15 79.19,15.419 6.745,15.72 8.14,15.765 10.68,15.765 13.22,15.765 81.628,15.782 84.168,15.782 62.275,15.85 16.5,15.875 65.003,15.872 67.675,15.9 68.688,15.9 69.7,15.9 72.05,16.1 5.475,16.355 78.44,16.844 74.125,16.9 6.745,16.99 44.135,17.015 46.675,17.015 49.215,17.015 51.755,17.015 82.898,17.053 30.003,17.077 22.677,17.55 5.475,17.625 8.015,17.625 76.275,18 78.44,18.044 6.745,18.26 53.025,18.285 9.41,18.305 11.95,18.305 14.49,18.305 22.11,18.305 24.65,18.305 81.628,18.322 82.898,18.322 84.168,18.322 69.05,18.725 70.95,18.825 5.475,18.895 8.015,18.895 73.075,18.95 61.15,19 13.99,19.025 84.79,19.149 58.825,19.275 15.609,19.329 13.095,19.395 21.855,19.4 24.52,19.4 6.745,19.53 9.285,19.53 11.825,19.53 53.025,19.62 78.515,19.656 79.29,19.656 75.8,19.675 84.79,20.079 5.475,20.165 8.015,20.165 10.555,20.165 17.475,20.425 78.515,20.5 79.29,20.5 30.945,20.625 54.675,20.64 6.745,20.8 9.285,20.8 11.825,20.8 23.38,20.845 53.86,20.845 84.79,21.009 20.99,21.169 22.653,21.169 24.328,21.169 25.825,21.169 69.025,21.229 78.515,21.344 79.29,21.344 58.425,21.35 5.475,21.435 8.015,21.435 10.555,21.435 60.095,21.525 61.355,21.525 53.025,21.91 84.79,21.939 6.745,22.07 9.285,22.07 11.825,22.07 5.475,22.705 8.015,22.705 10.555,22.705 25.175,22.7 82.228,22.697 83.498,22.697 84.79,22.697 78.15,22.825 23.19,22.888 71.693,22.911 69.025,23.007 18.2,23.025 12.92,23.06 54.675,23.18 6.745,23.34 9.285,23.34 11.825,23.34 72.91,23.385 75.45,23.385 83.07,23.385 76.466,23.659 79.265,23.856 10.805,23.975 5.475,24.085 8.015,24.085 57.5,24.175 69.025,24.286 61.3,24.3 25.725,24.4 11.825,24.46 53.025,24.45 6.745,24.72 9.285,24.72 60.075,24.95 13.55,25.15 17.34,25.2 18.54,25.2 19.74,25.2 20.94,25.2 10.805,25.245 12.665,25.425 61.3,25.55 54.675,25.72 69.025,25.814 53.86,25.925 76.72,25.925 79.26,25.925 82.215,25.925 84.34,25.925 17.34,26.4 19.74,26.4 20.94,26.4 29.925,26.425 10.555,26.925 53.025,26.99 13.095,27.125 6.745,27.26 9.285,27.26 60.095,27.275 61.355,27.275 69.025,27.343 17.34,27.6 18.54,27.6 19.74,27.6 20.94,27.6 14.39,27.725 11.825,27.76 5.475,27.895 8.015,27.895 10.555,27.895 13.49,27.9 72.45,27.95 54.675,28.26 75.45,28.465 77.99,28.465 83.07,28.465 6.745,28.53 9.285,28.53 71.75,28.775 17.34,28.8 18.54,28.8 19.74,28.8 20.94,28.8 69.025,28.871 23.15,28.925 11.965,29.025 29.875,29.125 0.52,29.165 2.935,29.165 5.475,29.165 8.015,29.165 10.555,29.165 28.5,29.325 53.025,29.53 56.775,29.525 72.638,29.562 1.665,29.8 4.205,29.8 6.745,29.8 9.285,29.8 57.225,30.2 61.3,30.3 69.025,30.325 0.52,30.435 2.935,30.435 5.475,30.435 8.015,30.435 10.555,30.435 15.54,30.75 54.675,30.8 28.46,31.005 31,31.005 53.86,31.005 79.26,31.005 81.8,31.005 60.55,31.025 1.665,31.07 69.825,31.075 25.775,31.275 74.925,31.325 72.85,31.375 0.52,31.705 2.935,31.705 5.475,31.705 60.55,31.875 68.096,31.931 68.875,31.929 53.025,32.07 71.85,32.4 19.59,32.425 15.215,32.525 56.7,32.625 18.165,32.7 18.89,32.875 5.475,32.975 21.89,33.2 23.065,33.2 24.125,33.2 54.675,33.34 11.7,33.5 1.79,33.545 4.33,33.545 15.975,33.55 19.57,33.545 27.735,33.55 29.73,33.545 76.925,33.55 80.53,33.545 83.07,33.545 68.096,33.656 68.675,34.2 5.475,34.245 15.575,34.25 72.275,34.35 19.55,34.4 11.7,34.625 53.025,34.61 69.225,34.8 59.571,34.956 21.8,35.25 23.2,35.25 5.475,35.515 14.65,35.625 31.2,35.975 0.52,36.085 3.06,36.085 25.92,36.085 28.46,36.085 79.26,36.085 81.8,36.085 69.975,36.125 76.975,36.175 38.05,36.65 42.165,36.65 45.67,36.65 5.475,36.785 22.875,37.075 10.075,37.5 20.125,37.675 5.475,38.055 69.975,38.475 1.79,38.625 4.33,38.625 6.87,38.625 8.775,38.625 10.85,38.625 14.49,38.625 80.53,38.625 83.07,38.625 58.225,38.8 75.85,38.8 21.75,39.25 33.925,39.25 54.225,39.35 55.225,39.35 39.85,39.85 24.25,39.875 69.975,40.425 71.728,40.572 15.025,40.625 40.9,40.65 31,40.9 75.625,40.925 20.15,40.95 22,40.95 24.25,41.025 26.875,41.025 3.06,41.165 13.22,41.165 48.78,41.165 51.32,41.165 58.94,41.165 79.26,41.165 81.8,41.165 76.075,42.399 35.575,42.555 54.7,43.15 55.7,43.15 26.125,43.25 20.175,43.35 38.9,43.4 3.06,43.705 11.95,43.705 14.49,43.705 77.99,43.705 80.53,43.705 83.07,43.705 28.725,43.95 66.4,43.975 45.175,44 55.825,44.425 56.675,44.425 73.575,44.7 74.675,44.7 25.35,44.9 20.875,45.075 15.4,45.1 18.678,45.222 26.675,45.3 24.225,45.35 73.575,45.8 74.675,45.8 16.25,45.925 21.15,46 53.1,46.025 44.75,46.15 3.06,46.245 8.14,46.245 10.68,46.245 18.3,46.245 69.1,46.245 28.975,46.325 57.85,46.575 34.375,46.6 38.875,46.625 43.4,46.65 53.1,46.675 30.875,46.775 25.025,47.35 59.875,47.35 61.5,47.35 62.425,47.35 63.275,47.35 21.5,47.375 32.95,47.45 13.788,47.9 20.925,48.6 57.825,48.6 48.7,48.675 9.41,48.785 11.95,48.785 17.03,48.785 70.37,48.785 83.07,48.785 50.94,49.425 24.6,49.875 21.5,49.9 61.475,49.9 62.8,49.9 64.1,49.9 68.5,50.075 48.7,50.3 57.875,50.625 17.1,50.7 53.4,51.1 54.125,51.1 41.725,51.225 50.45,51.3 3.06,51.325 8.14,51.325 10.68,51.325 13.22,51.325 38.62,51.325 69.1,51.325 74.18,51.325 76.72,51.325 79.26,51.325 81.8,51.325 68.475,51.85 48.7,51.925 50.45,52.05 51.925,52.05 52.675,52.05 53.4,52.05 57.9,52.225 17.125,52.45 22.825,52.725 62.85,52.725 46.525,52.95 13.095,53.325 67.025,53.4 69.115,53.4 16.465,53.45 18.3,53.45 28.46,53.45 31,53.45 33.54,53.45 48.065,53.45 55.615,53.45 58.155,53.45
LW_BLUE: Q1.3 R95.1 R98.1 TP39.1 | length 4.5
  Top Layer w0.175: Q1.3@34.625,41.65 34.8,41.65 34.8,40.745 35.38,40.745 35.695,40.43 R95.1@35.695,38.66 R98.1@35.08,38.66
LW_GREEN: Q15.6 R94.1 R97.1 TP38.1 | length 4.7
  Top Layer w0.2: R97.1@37.54,38.66 R94.1@38.155,38.66 38.535,38.66 TP38.1@39.025,39.15 39.025,39.95 38.375,40.6 38.325,40.6 38.25,40.675 Q15.6@38.25,40.75 ; Q15.6@38.075,41.65 38.25,41.65 38.25,40.745 Q15.6@38.25,40.73
LW_RED: Q15.3 R93.1 R96.1 TP37.1 | length 5.9
  Top Layer w0.175: R93.1@36.925,38.66 R96.1@36.31,38.66 36.31,40.625 35.9,41.035 TP37.1@35.9,41.65 Q15.3@36.95,41.65 ; Q15.3@36.95,42.555 Q15.3@36.95,41.65 ; Q15.3@37.075,41.65 Q15.3@36.95,41.65
N2V0: C9.1 C11.1 C14.1 C15.1 C16.1 C44.2 D5.2 R12.2 R79.1 TP18.1 U2.10 | length 46.3
  Top Layer w0.2: C15.1@73.21,33.356 C16.1@74.39,33.356 ; C14.1@73.21,39.748 v1(73.8,39.748) ; v1(73.787,33.368) 73.794,33.375 73.794,34.3 U2.10@73.8,34.306 ; R12.2@74.39,39.106 C9.1@73.785,39.106 73.792,39.114 73.792,39.74 v1(73.8,39.748) ; C11.1@74.39,39.748 v1(73.8,39.748)
  Bottom Layer w0.6: v1(49.575,51.175) v1(49.575,51.875) 49.575,52.549 50.027,53 54.425,53 v1(56.85,50.575) v1(56.85,49.75) 58.2,49.75 59.7,48.25 68.75,48.25 70.35,46.65 70.35,43.198 v1(73.8,39.748) ; v1(73.787,33.368) 75.725,35.306 75.725,37.825 v1@73.802,39.748
NetC1_1: C1.1 R1.1 R3.2 U1.12 | length 4.3
  Top Layer w0.2: C1.1@65.356,39.931 R1.1@65.356,39.156 65.356,39.141 66.346,38.151 66.346,37.881 ; U1.12@66.346,37.156 66.346,37.881 ; R3.2@67.436,37.756 66.471,37.756 66.346,37.881
NetC6_2: C6.2 R7.2 R10.2 U1.11 | length 2.4
  Top Layer w0.2: U1.11@66.346,36.506 66.355,36.498 67.428,36.498 R10.2@67.436,36.49 ; C6.2@67.436,35.856 R10.2@67.436,36.49 ; R7.2@67.436,37.123 R10.2@67.436,36.49
NetC7_2: C7.2 R4.2 R11.1 R20.1 R25.1 R29.1 TP4.1 | length 26.9
  Top Layer w0.15: C7.2@66.96,40.444 R4.2@66.96,41.081 70.619,41.081 TP4.1@70.625,41.075 70.635,41.065 R20.1@70.635,37.156 70.625,37.146 70.625,35.216 R25.1@70.615,35.206 70.615,32.435 72.325,30.725 75.875,30.725 77.535,32.385 R29.1@77.535,34.306 R11.1@77.535,38.056
NetC11_2: C11.2 R12.1 R13.2 R15.1 U2.2 | length 3.7
  Top Layer w0.2: U2.2@74.45,38.056 74.45,38.381 74.96,38.891 C11.2@74.96,39.606 ; R12.1@74.96,39.106 R15.1@74.96,41.031
NetC14_2: C14.2 R21.1 R23.2 R24.1 U2.4 | length 3.7
  Top Layer w0.2: R24.1@72.64,40.248 C14.2@72.64,39.748 ; R21.1@72.64,41.031 C14.2@72.64,39.748 ; U2.4@73.15,38.056 73.135,38.071 73.135,38.396 72.64,38.891 C14.2@72.64,39.748
NetC15_2: C15.2 R26.1 R27.2 R28.1 U2.9 | length 3.1
  Top Layer w0.2: R26.1@72.01,33.356 C15.2@72.64,33.356 ; R28.1@72.64,32.006 C15.2@72.64,33.356 ; U2.9@73.15,34.306 73.15,33.981 72.675,33.506 72.675,33.391 C15.2@72.64,33.356
NetC16_2: C16.2 R30.1 R31.2 R32.1 U2.11 | length 3.2
  Top Layer w0.2: U2.11@74.45,34.306 74.45,33.954 74.96,33.444 C16.2@74.96,33.356 ; R30.1@74.96,32.006 C16.2@74.96,33.356 ; R31.2@75.6,33.356 C16.2@74.96,33.356
NetC21_1: C21.1 Q5.3 R42.1 | length 5.5
  Top Layer w0.3: Q5.3@65.446,27.603 Q5.3@64.796,27.603 64.796,28.548 Q5.3@64.796,29.493 Q5.3@65.446,29.493
  Top Layer w0.5: R42.1@63.646,28.171 C21.1@63.646,29.031 ; 63.696,28.548 64.796,28.548 Q5.3@65.121,28.548
NetC22_1: C22.1 Q7.3 R46.1 | length 5.5
  Top Layer w0.3: Q7.3@65.446,24.645 Q7.3@64.796,24.645 64.796,25.59 Q7.3@64.796,26.535 Q7.3@65.446,26.535
  Top Layer w0.5: R46.1@63.646,25.213 C22.1@63.646,26.073 ; 63.696,25.59 64.796,25.59 Q7.3@65.121,25.59
NetC23_1: C23.1 Q9.3 R50.1 | length 6
  Top Layer w0.3: R50.1@63.646,22.246 63.696,22.296 63.696,22.714 ; Q9.3@65.446,21.686 Q9.3@64.796,21.686 64.796,22.631 Q9.3@64.796,23.576 Q9.3@65.446,23.576
  Top Layer w0.5: R50.1@63.646,22.246 C23.1@63.646,23.106 ; 63.696,22.714 63.779,22.631 64.796,22.631 Q9.3@65.121,22.631
NetC24_1: C24.1 Q10.3 R54.2 | length 6
  Top Layer w0.3: R54.2@63.646,19.296 63.696,19.346 63.696,19.764 ; Q10.3@65.446,18.736 Q10.3@64.796,18.736 64.796,19.681 Q10.3@64.796,20.626 Q10.3@65.446,20.626
  Top Layer w0.5: R54.2@63.646,19.296 C24.1@63.646,20.156 ; 63.696,19.764 63.779,19.681 64.796,19.681 Q10.3@65.121,19.681
NetC29_1: C29.1 J1.6@59.5,51.275 J1.6@59.6,48.825 J1.6@61.6,51.275 J1.6@64,51.275 J1.6@66,48.825 J1.6@66.1,51.275 R63.1 | length 8.9
  Top Layer w0.15: J1.6@59.5,51.275 J1.6@61.6,51.275 J1.6@64,51.275 J1.6@66.1,51.275 ; J1.6@66.075,51.272 66.082,51.265 R63.1@67.75,51.265 C29.1@67.75,50.66
NetC33_1: C33.1 J2.6@19.5,51.275 J2.6@19.6,48.825 J2.6@21.6,51.275 J2.6@24,51.275 J2.6@26,48.825 J2.6@26.1,51.275 R70.1 | length 8.9
  Top Layer w0.15: C33.1@17.85,51.88 R70.1@17.85,51.275 J2.6@19.5,51.275 J2.6@21.6,51.275 J2.6@24,51.275 J2.6@26.1,51.275
NetC37_2: C37.2 R74.1 | length 0.7
  Top Layer w0.175: C37.2@49.4,44.805 R74.1@50.125,44.805
NetC40_2: C40.2 R76.2 U5.E3 | length 2.3
  Top Layer w0.175: R76.2@49.55,48.225 49.575,48.2 49.575,47.725 ; C40.2@49.575,47.25 49.575,47.725 ; U5.E3@50.9,47.725 49.575,47.725
NetC42_2: C42.2 R78.1 | length 0.7
  Top Layer w0.175: R78.1@50.4,50.61 C42.2@51.1,50.61
NetC45_1: C45.1 R71.1 | length 0.6
  Top Layer w0.2: C45.1@57.2,41.42 R71.1@57.2,41.98
NetC70_1: C70.1 U12.N24 | length 2.9
  Top Layer w0.25: C70.1@13.74,29 13.865,28.875 14.15,28.875 15.77,27.255 15.885,27.255 U12.N24@15.89,27.25
NetC71_1: C71.1 U12.AC5 | length 3
  Top Layer w0.184: U12.AC5@21.14,29.75 21.265,29.875 22.045,29.875 22.298,30.128 22.545,30.375
  Top Layer w0.25: 22.545,30.375 23.065,30.895 C71.1@23.065,31.45
NetD4_2: D4.2 L1.2 U5.A3 U5.B3 | length 0.8
  Top Layer w0.2: U5.B3@52.1,47.725 U5.A3@52.5,47.725 52.95,47.725
NetD5_1: D5.1 L2.2 U5.A2 | length 2.1
  Top Layer w0.2: U5.A2@52.5,48.125 53.325,48.125 53.775,48.575 L2.2@54.375,48.575
NetL3_1: L3.1 U8.4 | length 0.4
  Top Layer w0.2: U8.4@80.24,20.994 U8.4@80.64,20.994
NetL3_2: L3.2 U8.2
NetLD3_3: LD3.3 R94.2 | length 6.5
  Top Layer w0.2: R94.2@38.155,38.09 39.34,38.09 41.9,40.65 LD3.3@41.9,42.3
NetLD3_4: LD3.4 R93.2 | length 9.2
  Top Layer w0.2: v2(36.925,37.73) R93.2@36.925,38.09
  Top Layer w0.254: v1(42.8,40.825) LD3.4@42.8,42.3
  Mid-Layer 1 w0.2: v2(36.925,37.73) 40.11,37.73 42.8,40.42 v1(42.8,40.825)
NetLD3_5: LD3.5 R95.2 | length 11.6
  Top Layer w0.2: v2(35.695,37.53) R95.2@35.695,38.09
  Top Layer w0.254: v1(43.7,40.825) LD3.5@43.7,42.3
  Mid-Layer 1 w0.2: v2(35.695,37.53) 35.92,37.305 40.18,37.305 v1(43.7,40.825)
NetLD4_3: LD4.3 R97.2 | length 39.9
  Top Layer w0.2: R97.2@37.54,38.09 37.54,37.14 cw(c36.935,37.14) 36.935,36.535 34.73,36.535 ccw(c34.73,34.56) 32.755,34.56 32.755,19.455 ccw(c34.755,19.455) 34.755,17.455 41.336,17.455 cw(c41.336,14.216) 44.575,14.216 LD4.3@44.575,11.4
NetLD4_4: LD4.4 R96.2 | length 38.5
  Top Layer w0.2: R96.2@36.31,38.09 36.31,37.542 cw(c35.653,37.542) 35.653,36.885 34.705,36.885 ccw(c34.705,34.585) 32.405,34.585 32.405,19.405 ccw(c34.705,19.405) 34.705,17.105 41.195,17.105 cw(c41.195,14.625) 43.675,14.625 LD4.4@43.675,11.4
NetLD4_5: LD4.5 R98.2 | length 37.3
  Top Layer w0.2: R98.2@35.08,38.09 35.08,37.66 cw(c34.655,37.66) 34.655,37.235 ccw(c34.655,34.635) 32.055,34.635 32.055,19.355 ccw(c34.655,19.355) 34.655,16.755 40.925,16.755 cw(c40.925,14.88) 42.8,14.88 42.8,11.425 LD4.5@42.775,11.4
NetQ1_6: Q1.6 Q2.2 Q2.5 R37.2 | length 58.1
  Top Layer w0.2: v1(31.225,36.875) 31.225,40.156 32.719,41.65 33.675,41.65 33.5,41.65 Q1.6@33.5,42.555 ; v1(58.075,20.1) 58.075,19.101 58.625,18.55 59.925,18.55 60.263,18.212 v2(60.263,17.445) 59.805,17.445 R37.2@59.8,17.44 ; Q2.5@63.726,15.556 Q2.2@63.726,16.206 v2(63.726,16.612)
  Mid-Layer 1 w0.2: v2(60.263,17.445) 60.758,16.95 63.384,16.95 63.721,16.612 v2(63.726,16.612)
  Bottom Layer w0.2: v1(31.225,36.875) 31.675,37.325 52.468,37.325 55.8,33.993 55.8,22.375 v1(58.075,20.1)
NetQ3_1: Q3.1 Q13.1 SW1.2 | length 26.2
  Top Layer w0.2: SW1.2@42.8,51.6 42.8,51.3 43.75,50.35 43.75,48.375 44.525,47.6 v1(46.925,47.6) ; v1(58.65,46.575) 58.653,46.572 59.222,46.572 Q13.1@59.225,46.57 ; v1(63.175,43.95) Q3.1@63.175,44.68
  Bottom Layer w0.2: v1(46.925,47.6) 46.935,47.59 57.635,47.59 v1(58.65,46.575) 61.275,43.95 v1(63.175,43.95)
NetQ4_3: Q4.3 R58.2 | length 4.6
  Top Layer w0.254: Q4.3@58.285,28 59.015,28 59.19,28.175 59.19,27.025 59.823,26.392 R58.2@61.436,26.392
NetQ4_6: Q4.6 R40.1 | length 1.9
  Top Layer w0.15: Q4.6@59.19,29.125 Q4.6@59.365,29.3 ; R40.1@60.981,29.291 R40.1@60.996,29.306
  Top Layer w0.254: Q4.6@59.365,29.3 60.095,29.3 60.098,29.303 60.969,29.303 R40.1@60.981,29.291
NetQ5_1: Q5.1 R44.2 | length 0.8
  Top Layer w0.2: Q5.1@66.096,27.603 66.101,27.608 66.916,27.608 R44.2@66.921,27.613
NetQ6_2: Q6.2 R45.1 | length 0.8
  Top Layer w0.15: R45.1@70.935,28.768 R45.1@70.935,28.718 70.935,27.988 Q6.2@70.975,27.948
NetQ6_5: Q6.5 R49.1 | length 0.8
  Top Layer w0.15: R49.1@70.935,25.368 70.955,25.388 70.955,26.118 Q6.5@70.975,26.138
NetQ7_1: Q7.1 R48.2 | length 0.8
  Top Layer w0.2: Q7.1@66.096,24.645 66.101,24.65 66.916,24.65 R48.2@66.921,24.655
NetQ8_2: Q8.2 R53.1 | length 0.8
  Top Layer w0.15: R53.1@70.935,22.851 70.955,22.831 70.955,22.051 Q8.2@70.975,22.031
NetQ8_5: Q8.5 R57.1 | length 0.8
  Top Layer w0.2: R57.1@70.935,19.451 70.955,19.471 70.955,20.201 Q8.5@70.975,20.221
NetQ9_1: Q9.1 R52.2 | length 0.8
  Top Layer w0.25: Q9.1@66.096,21.686 66.101,21.691 66.916,21.691 R52.2@66.921,21.696
NetQ10_1: Q10.1 R56.2 | length 0.8
  Top Layer w0.2: Q10.1@66.096,18.736 66.101,18.741 66.916,18.741 R56.2@66.921,18.746
NetQ11_3: Q11.3 R38.1 | length 3.2
  Top Layer w0.25: Q11.3@58.46,22.125 Q11.3@59.19,22.125 ; Q11.3@59.19,22.3 Q11.3@59.19,22.125 ; Q11.3@59.365,22.3 Q11.3@59.19,22.125 ; R38.1@59.89,20.375 59.89,20.475 59.19,21.175 Q11.3@59.19,22.125
NetQ11_6: Q11.6 R33.2 | length 1.9
  Top Layer w0.3: Q11.6@59.19,23.25 59.365,23.425 60.095,23.425 R33.2@61.021,23.425
NetQ12_1: Q12.1 Q18.1 SW1.5 | length 15.2
  Top Layer w0.2: Q12.1@30.325,50.695 v1(30.325,51.425) ; Q18.1@34.278,48.803 v1@34.847,48.803 ; v1(41.975,48.8) SW1.5@42.8,48.8 SW1.5@42.8,48.5
  Bottom Layer w0.2: v1(30.325,51.425) 32.95,48.8 v1(34.85,48.8) v1(41.975,48.8)
NetQ14_2: Q14.2 Q14.5 Q17.6 R104.1 | length 9.6
  Top Layer w0.2: Q17.6@59.19,16.35 Q17.6@59.2,16.36 ; R104.1@59.2,17.44 Q17.6@59.2,16.36 ; v2(60.725,16.525) 60.095,16.525 59.365,16.525 Q17.6@59.2,16.36 ; Q14.5@66.266,15.556 Q14.2@66.266,16.206 v2(66.266,16.612)
  Mid-Layer 1 w0.2: v2(60.725,16.525) 63.075,16.525 63.425,16.175 64.175,16.175 64.612,16.612 v2(66.266,16.612)
NetQ16_2: Q16.2 Q16.5 Q17.3 R105.1 | length 23.2
  Top Layer w0.15: Q16.2@70.631,17.519 Q16.5@71.281,17.519
  Top Layer w0.2: R105.1@58.6,17.44 57.69,17.44 56.925,16.675 56.925,15.15 57.275,14.8 57.845,14.8 58.27,15.225 58.285,15.225 59.19,15.225 Q17.3@59.19,15.4 ; v1(59.2,13.925) Q17.3@59.2,15.225 ; Q16.5@71.281,17.519 v1(71.981,17.519)
  Bottom Layer w0.2: v1(59.2,13.925) 64.217,13.925 67.317,17.025 71.487,17.025 v1(71.981,17.519)
NetR2_1: R2.1 R5.2 U1.5 | length 2.1
  Top Layer w0.2: U1.5@63.496,34.306 63.496,33.981 63.496,33.213 63.528,33.181 63.551,33.181 63.586,33.146 R2.1@63.586,33.131 ; R2.1@63.621,33.056 63.771,32.906 63.771,32.878 63.918,32.731 63.946,32.731 64.165,32.513 64.165,32.498 R5.2@64.2,32.463
NetR2_2: R2.2 R3.1 U1.6 | length 7.6
  Top Layer w0.2: U1.6@64.146,34.306 64.146,33.631 64.151,33.626 64.151,33.136 R2.2@64.156,33.131 ; R3.1@68.006,37.756 v2(68.406,37.756)
  Mid-Layer 1 w0.2: v2(64.146,33.526) 64.176,33.526 66.341,35.691 v2(68.406,37.756)
NetR5_1: R5.1 R6.1 U1.8 | length 2.1
  Top Layer w0.2: R5.1@64.77,32.463 64.77,32.478 64.805,32.513 64.83,32.513 65.049,32.731 ; 65.05,32.731 65.196,32.878 ; 65.196,32.879 65.346,33.029 65.346,33.096 65.446,33.196 U1.8@65.446,34.306
NetR6_2: R6.2 R7.1 U1.7 | length 6.7
  Top Layer w0.2: U1.7@64.796,34.306 64.796,33.631 64.804,33.624 64.804,33.139 R6.2@64.811,33.131 ; R7.1@68.006,37.123 v2(68.406,37.123)
  Mid-Layer 1 w0.2: v2@64.802,33.518 v2(68.406,37.123)
  other v2: 64.796,33.524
